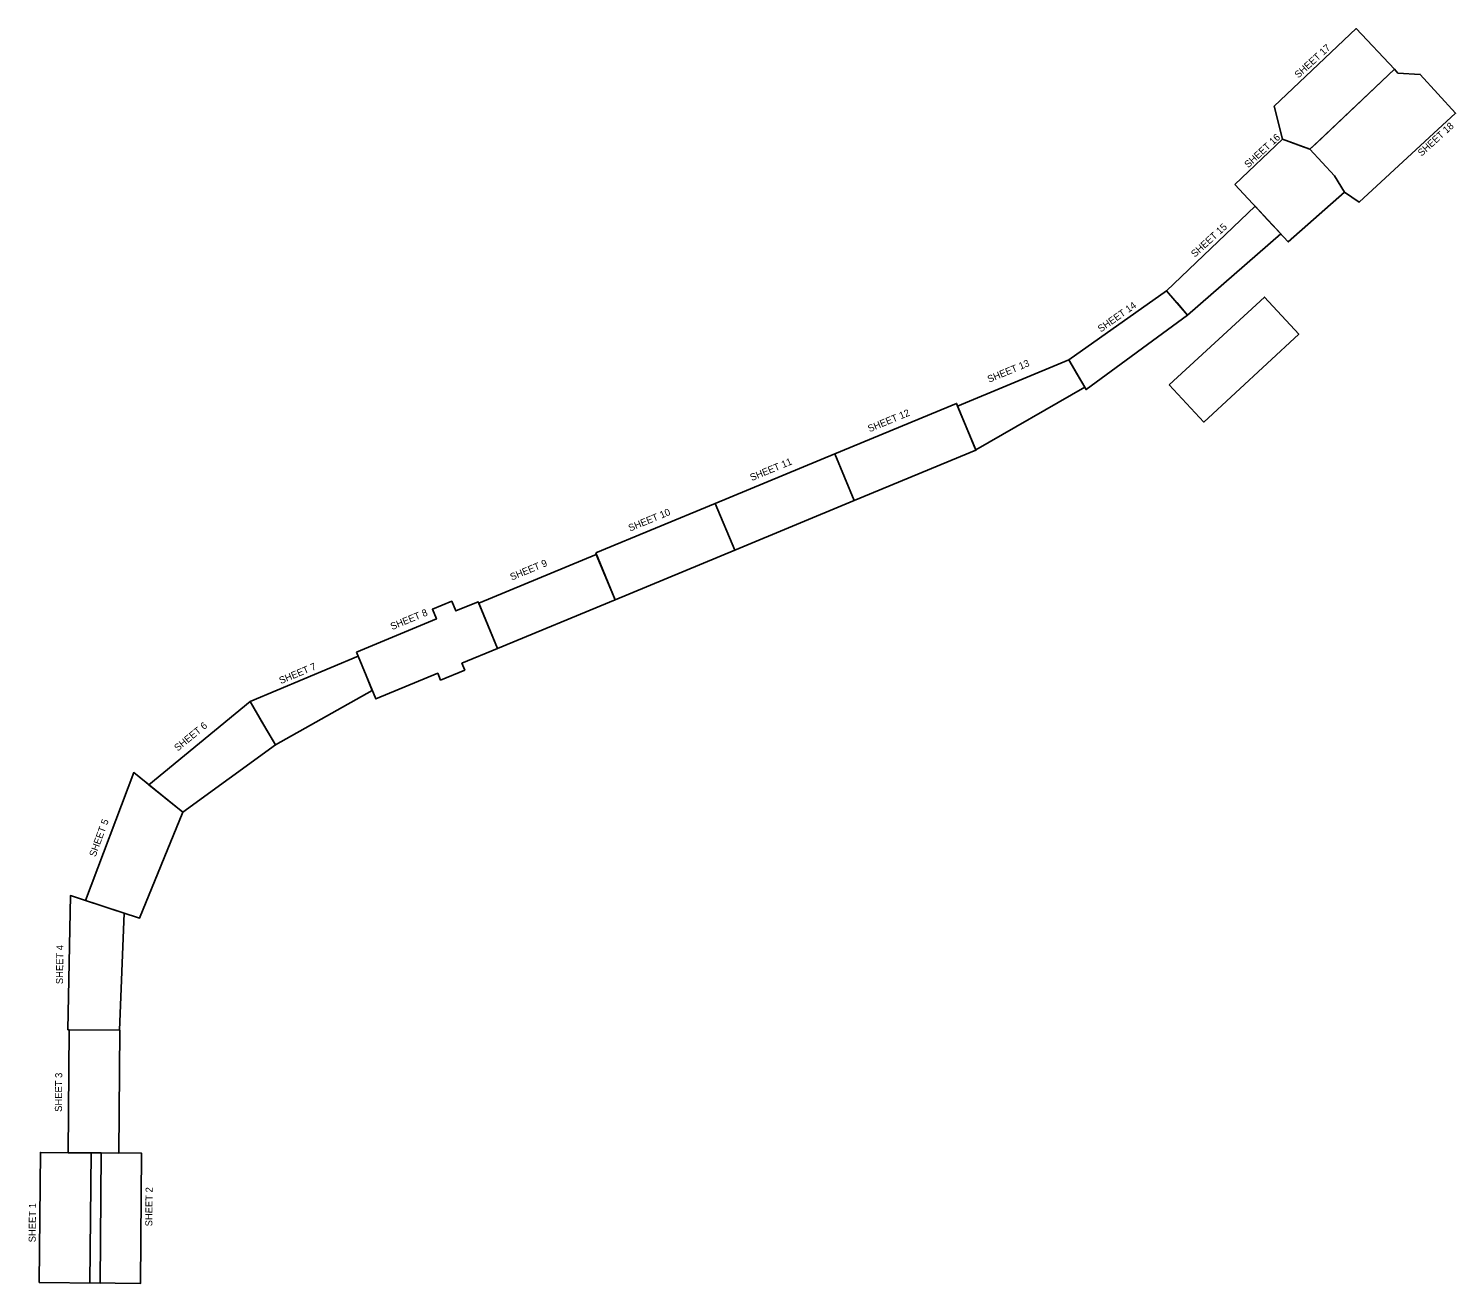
# Model space of a CAD drawing. Extents: x 590069 to 1729111, y 383148 to 773428.
# Drawn here: x 1712853 to 1729111, y 759135 to 773428 of the extents above; entities that cross this region are included whole.
import ezdxf

# ---------------------------------------------------------------- set-up
doc = ezdxf.new("R2010")
doc.units = 0
doc.layers.add('Z_SHEETCLIPS', color=7, linetype='Continuous')

msp = doc.modelspace()

# ---------------------------------------------------------------- linework, layer by layer
at = {"layer": 'Z_SHEETCLIPS'}
for p, q in [((1727121, 771088), (1726828, 771404)), ((1726058, 770165), (1725820, 770441)), ((1724903, 769316), (1724706, 769653)), ((1714610, 764501), (1714052, 764953))]:
    msp.add_line(p, q, dxfattribs=at)
for points in [[(1727453, 772054), (1727140, 772167), (1727045, 772544), (1727978, 773428), (1728415, 772966), (1727557, 772153)], [(1727845, 771564), (1727733, 771751), (1727453, 772054), (1727522, 772120), (1728415, 772966), (1728454, 772921), (1728709, 772906), (1729111, 772464), (1728013, 771449)], [(1726598, 771653), (1727140, 772167), (1727140, 772167), (1727344, 772093), (1727453, 772054), (1727733, 771751), (1727845, 771564), (1727205, 770997)], [(1725942, 770300), (1725820, 770441), (1726828, 771404), (1726967, 771254), (1727121, 771088), (1726058, 770165)], [(1725936, 770307), (1726058, 770165), (1724903, 769316), (1724793, 769503), (1724706, 769653), (1725820, 770441)], [(1725850, 769368), (1726933, 770370), (1727325, 769946), (1726242, 768945)], [(1723439, 769128), (1724706, 769653), (1724800, 769492), (1724887, 769343), (1723646, 768628)], [(1722041, 768584), (1723426, 769158), (1723647, 768625), (1722261, 768051)], [(1720678, 768020), (1722041, 768584), (1722261, 768051), (1720899, 767486)], [(1719315, 767455), (1720678, 768020), (1720899, 767486), (1719536, 766922)], [(1717982, 766884), (1719322, 767439), (1719536, 766922), (1718196, 766367)], [(1716590, 766326), (1717500, 766703), (1717455, 766813), (1717675, 766904), (1717720, 766794), (1717975, 766900), (1718196, 766367), (1717791, 766199), (1717824, 766121), (1717548, 766007), (1717516, 766085), (1716810, 765793)], [(1715532, 765500), (1715380, 765762), (1716609, 766280), (1716700, 766060), (1716770, 765890), (1715665, 765270)], [(1715513, 765532), (1715665, 765270), (1714610, 764501), (1714398, 764673), (1714225, 764813), (1715380, 765762)], [(1713504, 763496), (1714052, 764953), (1714455, 764627), (1714610, 764501), (1714118, 763297)], [(1713301, 762024), (1713330, 763552), (1713792, 763402), (1713944, 763353), (1713891, 762019)], [(1713304, 760624), (1713316, 762024), (1713894, 762019), (1713882, 760619)], [(1712975, 759145), (1712988, 760627), (1713681, 760621), (1713668, 759139)], [(1713552, 759140), (1713565, 760622), (1714142, 760617), (1714129, 759135)]]:
    msp.add_lwpolyline(points, close=True, dxfattribs=at)

# ---------------------------------------------------------------- texts
for s, rotation, p in [('SHEET 17', 42.3178, (1727320, 772858)), ('SHEET 16', 42.75, (1726750, 771835)), ('SHEET 18', 42.3178, (1728725, 771968)), ('SHEET 15', 42.3178, (1726142, 770818)), ('SHEET 14', 35.2868, (1725070, 769965)), ('SHEET 13', 22.5, (1723798, 769393)), ('SHEET 12', 22.5, (1722435, 768829)), ('SHEET 11', 22.5, (1721093, 768273)), ('SHEET 10', 22.5, (1719707, 767698)), ('SHEET 9', 22.5, (1718359, 767140)), ('SHEET 8', 22.5, (1716996, 766576)), ('SHEET 7', 22.836, (1715728, 765960)), ('SHEET 6', 39.4088, (1714553, 765192)), ('SHEET 5', 69.9323, (1713616, 763987)), ('SHEET 4', 89.5, (1713246, 762543)), ('SHEET 3', 89.5, (1713233, 761089)), ('SHEET 2', 89.5, (1714263, 759785)), ('SHEET 1', 89.5, (1712934, 759603))]:
    msp.add_text(s, height=80, rotation=rotation, dxfattribs=at).set_placement(p)

doc.saveas('drawing.dxf')
